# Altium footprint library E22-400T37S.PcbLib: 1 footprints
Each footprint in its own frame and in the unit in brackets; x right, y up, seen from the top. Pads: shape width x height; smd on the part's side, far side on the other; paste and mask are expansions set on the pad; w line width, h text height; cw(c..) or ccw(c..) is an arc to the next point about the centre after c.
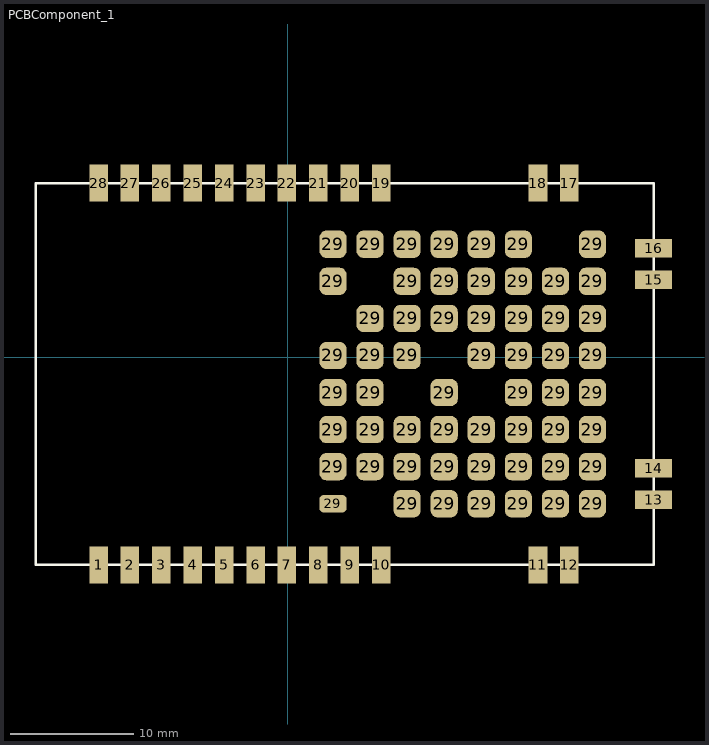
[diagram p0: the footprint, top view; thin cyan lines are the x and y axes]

## PCBComponent_1 [mm]
pads (85):
  rect 1.5x3 smd: 1(-15.291,-16.815) 2(-12.751,-16.815) 3(-10.211,-16.815) 4(-7.671,-16.815) 5(-5.131,-16.815) 6(-2.591,-16.815) 7(-0.051,-16.815) 8(2.489,-16.815) 9(5.029,-16.815) 10(7.569,-16.815) 11(20.269,-16.815) 12(22.809,-16.815) 17(22.809,14.085) 18(20.269,14.085) 19(7.569,14.085) 20(5.029,14.085) 21(2.489,14.085) 22(-0.051,14.085) 23(-2.591,14.085) 24(-5.131,14.085) 25(-7.671,14.085) 26(-10.211,14.085) 27(-12.751,14.085) 28(-15.291,14.085)
  rect 3x1.5 smd: 13(29.629,-11.525) 14(29.629,-8.985) 15(29.629,6.255) 16(29.629,8.795)
  rrect50% 2.2x1.4 smd: 29(3.679,-11.865)
  rrect50% 2.2x2.2 smd: 29(3.679,-8.865) 29(3.679,-5.865) 29(3.679,-2.865) 29(3.679,0.135) 29(3.679,6.135) 29(3.679,9.135) 29(6.679,-8.865) 29(6.679,-5.865) 29(6.679,-2.865) 29(6.679,0.135) 29(6.679,3.135) 29(6.679,9.135) 29(9.679,-11.865) 29(9.679,-8.865) 29(9.679,-5.865) 29(9.679,0.135) 29(9.679,3.135) 29(9.679,6.135) 29(9.679,9.135) 29(12.679,-11.865) 29(12.679,-8.865) 29(12.679,-5.865) 29(12.679,-2.865) 29(12.679,3.135) 29(12.679,6.135) 29(12.679,9.135) 29(15.679,-11.865) 29(15.679,-8.865) 29(15.679,-5.865) 29(15.679,0.135) 29(15.679,3.135) 29(15.679,6.135) 29(15.679,9.135) 29(18.679,-11.865) 29(18.679,-8.865) 29(18.679,-5.865) 29(18.679,-2.865) 29(18.679,0.135) 29(18.679,3.135) 29(18.679,6.135) 29(18.679,9.135) 29(21.679,-11.865) 29(21.679,-8.865) 29(21.679,-5.865) 29(21.679,-2.865) 29(21.679,0.135) 29(21.679,6.135) 29(21.679,3.135) 29(24.679,-11.865) 29(24.679,-8.865) 29(24.679,-5.865) 29(24.679,-2.865) 29(24.679,0.135) 29(24.679,3.135) 29(24.679,6.135) 29(24.679,9.135)
Top Overlay:
  lines w0.203: -20.371,-16.815 29.629,-16.815 ; -20.371,-16.815 -20.371,14.085 ; -20.371,-16.815 29.629,-16.815 ; -20.371,-16.815 -20.371,14.085 ; -20.371,14.085 29.629,14.085 ; -20.371,14.085 29.629,14.085 ; 29.629,-16.815 29.629,14.085 ; 29.629,-16.815 29.629,14.085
